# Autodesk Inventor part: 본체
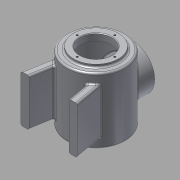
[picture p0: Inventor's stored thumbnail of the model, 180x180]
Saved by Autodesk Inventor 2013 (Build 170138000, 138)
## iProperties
Created: 2015-01
Part Number: 본체
Material: 알루미늄 6061
Document SubType Name: Modeling
Designer: Administrator
Mass: 1015.04 g
Surface Area: 1092.89 cm^2
Volume: 374.553 cm^3
Density: 2.71 g/cm^3
Author: Administrator
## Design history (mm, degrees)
sketch "스케치1"
  geometry: C1 r 50 at (0, 0); 1 further point
  constraints: 1 centre point, 1 coincident
  dimensions: "d0" = 50 radius of C1
extrude "돌출1" new body sketch "스케치1" stored distance "d1" = 112; taper "d2" = 0 deg
hole "구멍1" diameter "d6" = 54; stored, may be unused: countersink angle "d10" = 90 deg, drill point angle "d12" = 0 deg; dims "d4" = 10, "d5" = 10, "d7" = 6, "d8" = 54, "d9" = 8, "d11" = 8
sketch "스케치2"
  geometry: C1 r 45 at (0, 0); 1 further point
  constraints: 1 centre point, 1 coincident
  dimensions: "d13" = 45 radius of C1
extrude "돌출2" cut sketch "스케치2" distance "d14" = 97; taper "d15" = 0 deg
hole "구멍2" diameter "d18" = 54; stored, may be unused: countersink angle "d22" = 90 deg, drill point angle "d24" = 0 deg; dims "d16" = 10, "d17" = 10, "d19" = 6, "d20" = 54, "d21" = 8, "d23" = 8
sketch "스케치3"
  geometry: C1 r 38 at (0, 0); C2 r 27 at (0, 0) reference; 1 further point
  constraints: 1 centre point, 1 coincident
  dimensions: "d25" = 38 radius of C1
extrude "돌출3" join sketch "스케치3" distance "d26" = 5; taper "d27" = 0 deg
node "작업 평면1"
sketch "스케치4"
  geometry: C1 r 38 at (0, 0); 1 further point
  constraints: 1 centre point, 1 coincident
  dimensions: "d29" = 38 radius of C1
extrude "돌출4" join sketch "스케치4" stored distance "d30" = 5; taper "d31" = 0 deg
hole "구멍3" diameter "d34" = 54; stored, may be unused: countersink angle "d38" = 90 deg, drill point angle "d40" = 0 deg; dims "d32" = 10, "d33" = 10, "d35" = 6, "d36" = 54, "d37" = 8, "d39" = 30
sketch "스케치5"
  geometry: L1 (-138.91, -80)-(142.644, -80); L2 (-39.336, -30.865)-(-48, -80); L3 (-48, -80)-(-34, -80); L4 (-34, -80)-(-27.282, -41.901); L5 (0, 90.152)-(0, -105.867); L6 (39.336, -30.865)-(48, -80); L7 (48, -80)-(34, -80); L8 (34, -80)-(27.282, -41.901); A1 r 50 centre (0, 0) between (-39.336, -30.865) and (-27.282, -41.901); A2 r 50 centre (0, 0) between (27.282, -41.901) and (39.336, -30.865); 2 further points
  constraints: 16 end point, 4 point on circle, 4 symmetric about line, 3 point on line, 2 centre point, 1 coincident, 1 horizontal, 1 parallel, 1 perpendicular, 3 other
  dimensions: "d41" = 80 distance from line of point (0, 0) L1; "d42" = 14 distance of L2.end L3.end; "d43" = 48 horizontal distance of point (0, 0) L2.end; "d44" = 80 deg angle of L1 L4
extrude "돌출5" join sketch "스케치5" stored distance "d45" = 80; taper "d46" = 0 deg
sketch "스케치6"
  geometry: 5 further points
  constraints: 5 other
  dimensions: "d47" = 32 distance of point (0, 0) point (32, 0); "d48" = 0 vertical distance of point (32, 0) point (0, 0); "d51" = 360 deg dimension on point (0, 0) point (32, 0) (derived)
hole "구멍4" sketch "스케치6" at (32, 0), (0, 32), (-32, 0), (0, -32) diameter "d53" = 3.242; stored, may be unused: countersink angle "d57" = 90 deg, drill point angle "d59" = 118 deg; dims "d54" = 8, "d55" = 54, "d56" = 8, "d58" = 10
sketch "스케치7"
  geometry: 5 further points
  constraints: 1 vertical alignment, 5 other
  dimensions: "d63" = 360 deg dimension on point (0, 0) point (0, 32) (derived); "d88" = 32 distance of point (32, 0) point (0, 0)
hole "구멍5" sketch "스케치7" at (0, 32), (-32, 0), (0, -32), (32, 0) diameter "d65" = 3.242; stored, may be unused: countersink angle "d69" = 90 deg, drill point angle "d71" = 118 deg; dims "d66" = 8, "d67" = 54, "d68" = 8, "d70" = 10
node "작업 평면3"
  node "작업 평면2"
sketch "스케치8"
  geometry: L1 (-6, -26)-(6, -26); L2 (6, -26)-(6, 28); L3 (6, 28)-(-6, 28); L4 (-6, 28)-(-6, -26); L5 (-70.447, 1)-(22.592, 1); L6 (38, -61)-(-38, -61) reference; 1 further point
  constraints: 10 end point, 2 parallel, 2 perpendicular, 1 horizontal
  dimensions: "d73" = 12 distance between parallel lines of L2 L4; "d75" = 6 distance from line of L4 point (0, 0); "d76" = 54 distance of L3.end L1.start; "d77" = 27 distance between parallel lines of L3 L5; "d78" = 62 distance between parallel lines of L6 L5
extrude "돌출6" join sketch "스케치8" stored distance "d79" = 80; taper "d80" = 0 deg
sketch "스케치9"
  geometry: L1 (-26, -6)-(28, -6) reference; L2 (28, -6)-(28, 6) reference; 4 further points
  constraints: 2 midpoint, 1 horizontal alignment, 1 vertical alignment, 1 other
feature "엠보싱1" sketch "스케치9" dims "d81" = 0.5, "d82" = 0
fillet "모깎기1" dims "d83" = 3
fillet "모깎기2" dims "d84" = 3
fillet "모깎기3" dims "d85" = 3
fillet "모깎기4" dims "d86" = 3
fillet "모깎기5" dims "d87" = 3
chamfer "모따기1" distance "d89" = 1; stored, may be unused: second distance "d90" = 2, angle "d91" = 45 deg
fillet "모깎기6" dims "d92" = 3
node "솔리드1"
mirror "대칭1"
mirror "대칭2"
other parameters: "d28" = 62, "d72" = -2
